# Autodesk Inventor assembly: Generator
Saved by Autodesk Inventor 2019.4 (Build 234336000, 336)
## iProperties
Created: 2020-02
Part Number: Generator
Document SubType Name: Assembly
Designer: Administrator
Title: Generator v12
Author: Administrator
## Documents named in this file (2)
- c:\worker\convert-fusion-r01\tmp\job-1\5\output\files\e4333473-a38b-4431-9958-ad24a2f67704\Generator v12.iam
- c:\worker\convert-fusion-r01\tmp\job-1\5\output\files\e4333473-a38b-4431-9958-ad24a2f67704\Generator.ipt
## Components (1 placed, 1 different names)
1. Generator:1
